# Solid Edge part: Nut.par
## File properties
Author: Sarvanan
Template: sync iso part.par
Last saved by: Sarvanan
Revision: 6
Application: Solid Edge
Accuracy: 0.990
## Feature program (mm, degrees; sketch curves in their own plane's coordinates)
sketch for "Hole_1" plane through (21.0838, 43.6973, 8) normal (0, 0, 1) x-axis (1, 0, 0)
  hole centre (-1.3414, 0.2221) bore radius 6
hole "Hole_1" diameter 12 through
pattern "unnamed Pattern 1" of "Hole_1"
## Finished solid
Body 1: solid body, 21 faces, 56 edges, 36 vertices.
  Faces by surface: spun 12, plane 8, cylinder 1
  Edges by curve: circle 18, line 18, intersection 17, spline 3
Bounding box of the edges (mm; curved faces can reach further): 30.022 x 26.000 x 12.000, from (4.7313, 30.9194, 0) to (34.7535, 56.9194, 12).
Cylindrical faces by radius (mm): R6 x1
Planar faces by outward normal: +y 1, +z 1, -y 1, -z 1, oblique 4
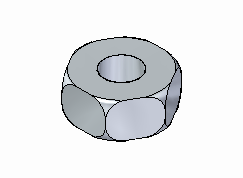
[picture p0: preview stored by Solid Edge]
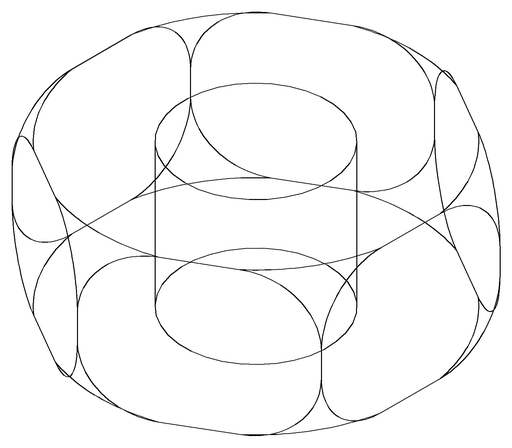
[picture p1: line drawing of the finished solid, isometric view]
